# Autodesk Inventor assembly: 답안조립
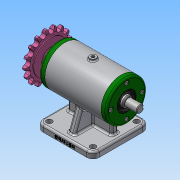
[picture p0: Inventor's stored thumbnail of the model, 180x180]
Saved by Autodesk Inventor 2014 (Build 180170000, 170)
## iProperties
Created: 2019-06
Part Number: 답안조립
Document SubType Name: Assembly
Designer: NET
Author: NET
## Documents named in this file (11)
- C:\Users\NET\Desktop\490604V1030\답안조립.iam
- C:\Users\NET\Desktop\490604V1030\답안본체.ipt
- C:\Users\NET\Desktop\490604V1030\축.ipt
- C:\Users\NET\Desktop\490604V1030\베어링 6203.ipt
- C:\Users\NET\Desktop\490604V1030\커버.ipt
- C:\Users\NET\Desktop\490604V1030\오일 실 17 30 5.ipt
- C:\Users\NET\Desktop\490604V1030\키 4x4x12.ipt
- C:\Users\NET\Desktop\490604V1030\스프로킷.ipt
- C:\Users\NET\Desktop\490604V1030\평와셔.ipt
- C:\Users\NET\Desktop\490604V1030\스프링와셔.ipt
- C:\Users\NET\Desktop\490604V1030\볼트 M4.ipt
